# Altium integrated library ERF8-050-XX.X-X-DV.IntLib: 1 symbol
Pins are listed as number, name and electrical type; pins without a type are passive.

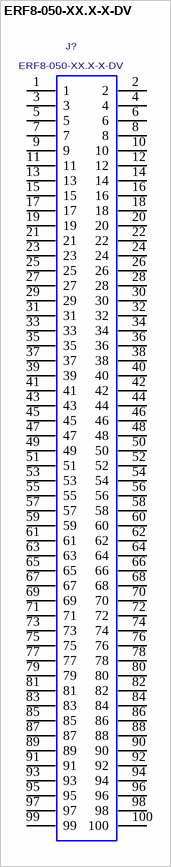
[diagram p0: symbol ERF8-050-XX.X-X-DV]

## ERF8-050-XX.X-X-DV
designator J?
Socket Assembly, Double Row Vertical, Surface Mount, 0.8mm Pitch, 100 Pins; MANUFACTURER: SAMTEC
footprint ERF8-050-XX.X-X-DV
pins: 1, 2, 3, 4, 5, 6, 7, 8, 9, 10, 11, 12, 13, 14, 15, 16, 17, 18, 19, 20, 21, 22, 23, 24, 25, 26, 27, 28, 29, 30, 31, 32, 33, 34, 35, 36, 37, 38, 39, 40, 41, 42, 43, 44, 45, 46, 47, 48, 49, 50, 51, 52, 53, 54, 55, 56, 57, 58, 59, 60, 61, 62, 63, 64, 65, 66, 67, 68, 69, 70, 71, 72, 73, 74, 75, 76, 77, 78, 79, 80, 81, 82, 83, 84, 85, 86, 87, 88, 89, 90, 91, 92, 93, 94, 95, 96, 97, 98, 99, 100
